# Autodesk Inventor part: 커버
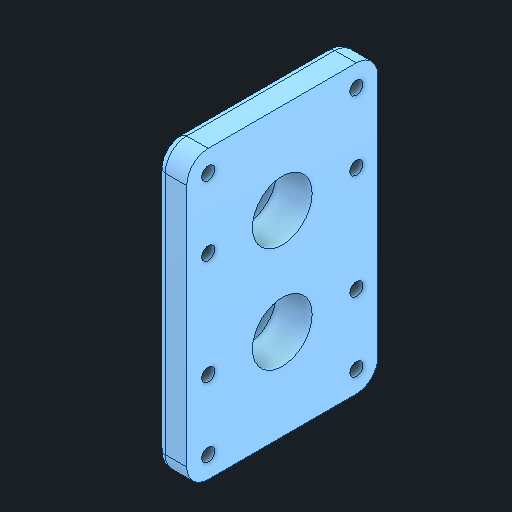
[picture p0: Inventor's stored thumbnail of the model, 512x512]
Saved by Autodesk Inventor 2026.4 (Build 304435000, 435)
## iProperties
Created: 2026-09
Part Number: 커버
Material: 알루미늄 6061
Document SubType Name: Modeling
Designer: user
Density: 2.71 g/cm^3
Appearance: 기본값
Author: jhkim
Sending System: Autodesk Inventor 2027
Preprocessor: ST-DEVELOPER v20.1
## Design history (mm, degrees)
feature "솔리드1"
node "솔리드2"
